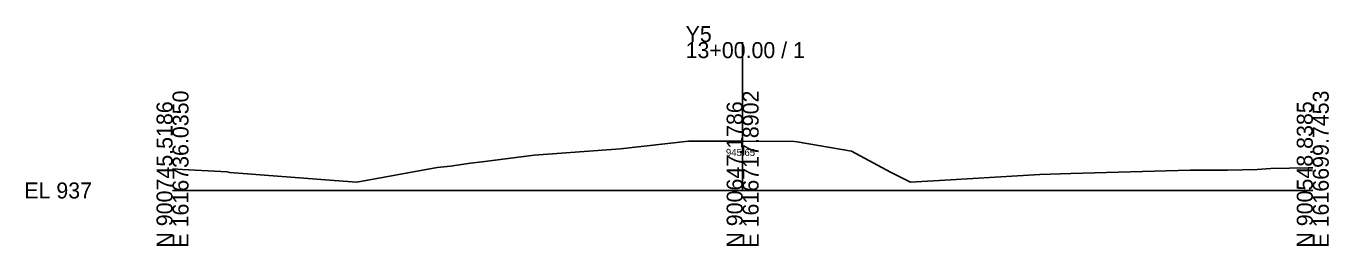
# Model space of a CAD drawing. Extents: x -26 to 1403, y -10 to 4517.
# Drawn here: x -25.7 to 202.8, y 2990.3 to 3028.8 of the extents above; entities that cross this region are included whole.
import ezdxf

# ---------------------------------------------------------------- set-up
doc = ezdxf.new("R2010")
doc.units = 0
for name, color, linetype in [('Exist Cross Section Cell', 7, 'Continuous'), ('Exist XS Center Line Elevation Label', 7, 'Continuous'), ('Exist XS Ground Line', 7, 'Continuous')]:
    doc.layers.add(name, color=color, linetype=linetype)

msp = doc.modelspace()

# ---------------------------------------------------------------- linework, layer by layer
at = {"layer": 'Exist Cross Section Cell'}
for p, q in [((100, 3000), (100, 3025.96)), ((0, 3000), (100, 3000)), ((100, 3000), (200, 3000))]:
    msp.add_line(p, q, dxfattribs=at)
at = {"layer": 'Exist XS Ground Line'}
for p, q in [((78.58, 3007.31), (90.52, 3008.63)), ((90.52, 3008.63), (99.41, 3008.65)), ((99.41, 3008.65), (99.77, 3008.65)), ((99.77, 3008.65), (100.12, 3008.65)), ((100.12, 3008.65), (109.07, 3008.59)), ((109.07, 3008.59), (109.57, 3008.51)), ((109.57, 3008.51), (119.07, 3006.87)), ((54.3, 3005.03), (63.41, 3006.17)), ((63.41, 3006.17), (78.58, 3007.31)), ((119.07, 3006.87), (125.96, 3003.2)), ((0, 3003.78), (1.74, 3003.65)), ((1.74, 3003.65), (9.57, 3003.25)), ((9.57, 3003.25), (10.06, 3003.17)), ((10.06, 3003.17), (28.33, 3001.75)), ((32.34, 3001.46), (46.43, 3004.05)), ((46.43, 3004.05), (48.75, 3004.27)), ((48.75, 3004.27), (52.28, 3004.76)), ((52.28, 3004.76), (54.3, 3005.03)), ((125.96, 3003.2), (129.44, 3001.44)), ((152.11, 3002.79), (157.55, 3002.95)), ((157.55, 3002.95), (178.52, 3003.53)), ((178.52, 3003.53), (185.05, 3003.57)), ((185.05, 3003.57), (190.27, 3003.7)), ((190.27, 3003.7), (192.62, 3003.86)), ((192.62, 3003.86), (199.2, 3003.98)), ((199.2, 3003.98), (200, 3003.99)), ((28.33, 3001.75), (32.34, 3001.46)), ((129.44, 3001.44), (136.43, 3001.86)), ((136.43, 3001.86), (152.11, 3002.79))]:
    msp.add_line(p, q, dxfattribs=at)

# ---------------------------------------------------------------- texts
at = {"layer": 'Exist Cross Section Cell'}
for s, p in [('Y5', (90, 3025.96)), ('13+00.00 / 1', (90, 3023.16)), ('EL 937', (-26, 2998.6))]:
    msp.add_text(s, height=2.8, dxfattribs=at).set_placement(p)
for s, p in [('E 1616736.0350', (2.8, 2990)), ('E 1616717.8902', (102.8, 2990)), ('E 1616699.7453', (202.8, 2990)), ('N 900745.5186', (0, 2990)), ('N 900647.1786', (100, 2990)), ('N 900548.8385', (200, 2990))]:
    msp.add_text(s, height=2.8, rotation=90, dxfattribs=at).set_placement(p)
at = {"layer": 'Exist XS Center Line Elevation Label'}
msp.add_text('945.65', height=1.25, dxfattribs=at).set_placement((97.07, 3006.03))

doc.saveas('drawing.dxf')
